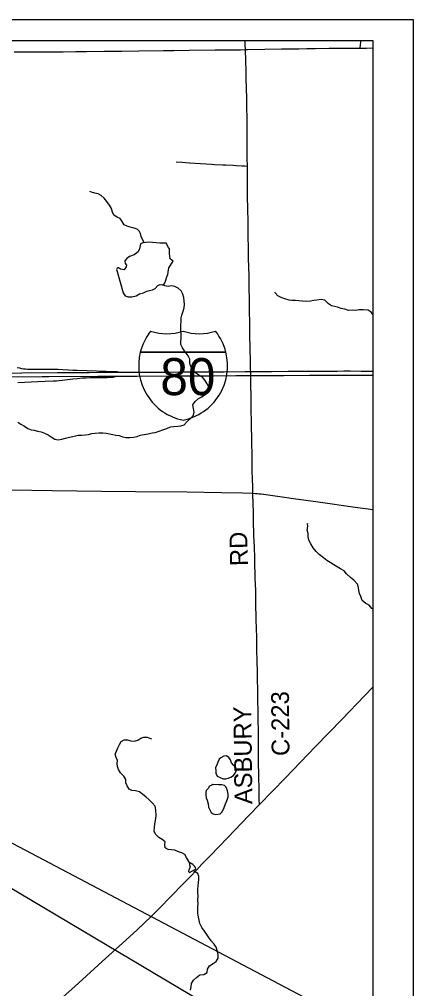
# Model space of a CAD drawing. Extents: x 0 to 34, y 0 to 22.
# Drawn here: x 28.741 to 30.033, y 13.678 to 16.775 of the extents above; entities that cross this region are included whole.
import ezdxf

# ---------------------------------------------------------------- set-up
doc = ezdxf.new("R2010")
doc.units = 0
for name, color, linetype in [('GM_X_Corporation', 7, 'Continuous'), ('GM_X_County_Road', 7, 'Continuous'), ('GM_X_County_Road_Text', 7, 'Continuous'), ('GM_X_Interchange_Ramps', 7, 'Continuous'), ('GM_X_Interstate_Location', 7, 'Continuous'), ('GM_X_Interstate_Route', 7, 'Continuous'), ('GM_X_Interstate_Shield', 7, 'Continuous'), ('GM_X_Minor_Lake', 7, 'Continuous'), ('GM_X_Minor_River', 7, 'Continuous'), ('GM_X_State_Route', 7, 'Continuous'), ('GM_X_Township_Road', 7, 'Continuous'), ('SH_Data', 7, 'Continuous'), ('SH_Text', 7, 'Continuous')]:
    doc.layers.add(name, color=color, linetype=linetype)

msp = doc.modelspace()

# ---------------------------------------------------------------- linework, layer by layer
at = {"layer": 'GM_X_Corporation'}
msp.add_lwpolyline([(29.8715, 12.7899), (29.8715, 16.7067), (27.8821, 16.7067), (27.8849, 16.5038), (27.88, 15.6409), (27.8801, 15.6288), (27.8823, 15.2828), (27.9019, 13.7865), (27.9109, 12.7769)], dxfattribs=at)
at = {"layer": 'GM_X_County_Road'}
for points in [[(28.7244, 16.671), (28.7735, 16.671), (28.8076, 16.6711), (28.8486, 16.6714), (28.8815, 16.6713), (28.9219, 16.672), (28.9561, 16.6725), (29.0126, 16.6733), (29.0692, 16.6736), (29.1232, 16.6741), (29.2022, 16.6749), (29.2345, 16.6754), (29.2838, 16.6762), (29.367, 16.6775), (29.4482, 16.678), (29.4634, 16.6785)], [(29.4634, 16.6785), (29.4699, 16.6787), (29.5251, 16.6795), (29.5792, 16.6803), (29.6053, 16.6807), (29.6345, 16.6812), (29.6593, 16.6814), (29.6873, 16.682), (29.7314, 16.6826), (29.7755, 16.6828), (29.8121, 16.6833), (29.827, 16.6832), (29.8302, 16.6833)], [(29.4698, 16.3059), (29.4696, 16.3314), (29.4694, 16.3737), (29.4691, 16.4147), (29.4687, 16.4632), (29.468, 16.4893), (29.4676, 16.5234), (29.4667, 16.5539), (29.466, 16.5874), (29.4654, 16.6104), (29.4646, 16.6415), (29.4634, 16.6785)], [(29.8302, 16.6833), (29.8506, 16.6834), (29.8715, 16.6844)], [(29.4874, 15.2604), (29.4867, 15.2815), (29.4861, 15.3051), (29.4854, 15.3337), (29.4847, 15.3673), (29.4835, 15.4375), (29.4833, 15.4728), (29.4829, 15.4964), (29.4823, 15.52), (29.4823, 15.5529), (29.4819, 15.5666), (29.4813, 15.6101), (29.481, 15.6231), (29.4807, 15.6368), (29.4807, 15.6393), (29.4804, 15.6497), (29.4803, 15.6561), (29.4797, 15.6759), (29.4793, 15.6921), (29.4789, 15.7144), (29.4783, 15.7355), (29.4778, 15.7536), (29.4774, 15.807), (29.4771, 15.8418), (29.4761, 15.8872), (29.476, 15.9096), (29.4753, 15.9301), (29.4752, 15.9537), (29.4743, 15.9866), (29.4739, 16.0083), (29.4731, 16.0512), (29.4727, 16.0748), (29.4726, 16.0935), (29.4722, 16.1308), (29.4713, 16.1674), (29.4706, 16.2115), (29.4702, 16.2687), (29.4698, 16.3059)], [(29.5086, 14.2655), (29.5079, 14.2809), (29.5075, 14.2902), (29.507, 14.3163), (29.5066, 14.3542), (29.5057, 14.4064), (29.5056, 14.4319), (29.5051, 14.4555), (29.5048, 14.4946), (29.504, 14.5437), (29.5039, 14.5667), (29.5033, 14.5978), (29.5029, 14.6288), (29.5021, 14.6692), (29.5017, 14.6928), (29.501, 14.7214), (29.5002, 14.7618), (29.4995, 14.8003), (29.4982, 14.8562), (29.4972, 14.9127), (29.4964, 14.951), (29.4952, 14.9877), (29.4947, 15.0045), (29.4938, 15.0306), (29.4931, 15.0548), (29.4924, 15.0871), (29.4909, 15.1268), (29.4896, 15.1741), (29.489, 15.2033), (29.4882, 15.2238), (29.4874, 15.2604)]]:
    msp.add_lwpolyline(points, dxfattribs=at)
at = {"layer": 'GM_X_Interchange_Ramps'}
for points in [[(28.7341, 15.6624), (28.7423, 15.6609), (28.7485, 15.6596), (28.7545, 15.6585), (28.7608, 15.6579), (28.7678, 15.6576), (28.7752, 15.6576), (28.8429, 15.6571), (28.8652, 15.6566), (28.8803, 15.656), (28.8981, 15.6552), (28.9118, 15.6544), (28.926, 15.6536), (28.9577, 15.6523), (29.0489, 15.6498), (29.0509, 15.6496), (29.0525, 15.6493), (29.0543, 15.6489), (29.0565, 15.6483), (29.0595, 15.6473)], [(28.737, 15.6146), (28.7583, 15.6154), (28.7789, 15.6162), (28.8001, 15.6173), (28.8239, 15.6184), (28.8507, 15.6197), (28.8605, 15.6202), (28.8687, 15.6208), (28.8785, 15.6216), (28.9125, 15.6257), (28.9267, 15.6273), (28.9427, 15.629), (28.95, 15.6297), (28.9552, 15.6299), (28.9666, 15.63), (28.9763, 15.63), (29.0028, 15.6301), (29.0214, 15.6305), (29.0358, 15.631), (29.0412, 15.6317), (29.0442, 15.6322), (29.0489, 15.6336), (29.0526, 15.6346)]]:
    msp.add_lwpolyline(points, dxfattribs=at)
at = {"layer": 'GM_X_Interstate_Route'}
for points in [[(28.6049, 15.6447), (28.7489, 15.6454), (28.8635, 15.6463), (28.964, 15.6468), (28.9948, 15.647), (29.0595, 15.6473), (29.1062, 15.6473), (29.2094, 15.6479), (29.2656, 15.6482), (29.2958, 15.6484), (29.3406, 15.6487), (29.3957, 15.649), (29.463, 15.6495), (29.4804, 15.6497), (29.495, 15.6498), (29.5466, 15.6501), (29.6004, 15.6503), (29.6301, 15.6504), (29.6796, 15.6507), (29.7571, 15.6512), (29.7779, 15.6514), (29.7981, 15.6513), (29.833, 15.6512), (29.8623, 15.6506), (29.8715, 15.6505)], [(28.4183, 15.6309), (28.5497, 15.6317), (28.6303, 15.6322), (28.7018, 15.6327), (28.8137, 15.6335), (28.835, 15.6337), (28.9922, 15.6344), (29.0526, 15.6346), (29.0786, 15.6347), (29.1177, 15.635), (29.2238, 15.6356), (29.2846, 15.6359), (29.359, 15.6363), (29.4331, 15.6366), (29.4807, 15.6368), (29.4864, 15.6368), (29.5351, 15.6371), (29.5866, 15.6373), (29.6684, 15.6378), (29.7399, 15.6382), (29.7723, 15.6384), (29.8513, 15.6383), (29.8631, 15.638), (29.8715, 15.6378)]]:
    msp.add_lwpolyline(points, dxfattribs=at)
at = {"layer": 'GM_X_Interstate_Shield'}
for p, q in [((29.1278, 15.7117), (29.4011, 15.7117)), ((29.4011, 15.7117), (29.1278, 15.7117)), ((29.4011, 15.7117), (29.1278, 15.7117))]:
    msp.add_line(p, q, dxfattribs=at)
for centre, start, end in [((29.3, 15.6681), 141.669, 165.8066), ((29.2126, 15.9481), 253.0091, 286.9909), ((29.3163, 15.9481), 253.0091, 286.9909), ((29.2289, 15.6681), 14.1934, 38.331), ((29.3, 15.6681), 165.8066, 258.463), ((29.2289, 15.6681), 281.537, 14.1934)]:
    msp.add_arc(centre, 0.1776, start, end, dxfattribs=at)
at = {"layer": 'GM_X_Minor_Lake'}
for p, q in [((29.0541, 15.969), (29.0726, 15.9012)), ((29.3738, 14.3564), (29.3925, 14.3483)), ((29.3771, 14.3291), (29.3593, 14.33)), ((29.2852, 14.0481), (29.3044, 14.059))]:
    msp.add_line(p, q, dxfattribs=at)
for points in [[(29.0726, 15.9012), (29.0796, 15.891), (29.0894, 15.8885), (29.1004, 15.8882), (29.114, 15.8918), (29.1249, 15.8973), (29.1378, 15.9012), (29.1491, 15.9067), (29.1574, 15.9087), (29.1672, 15.911), (29.1751, 15.9149), (29.1833, 15.9245), (29.1916, 15.9273), (29.1988, 15.9266), (29.2052, 15.9312), (29.2078, 15.9381), (29.2126, 15.9522), (29.2155, 15.9591), (29.217, 15.9667), (29.2191, 15.9808), (29.2329, 16.0018), (29.2233, 16.0101), (29.2208, 16.0271), (29.2214, 16.0419), (29.218, 16.0461), (29.2106, 16.0593), (29.1906, 16.0594), (29.1784, 16.0604), (29.1553, 16.0624), (29.136, 16.0611), (29.1281, 16.0572), (29.1256, 16.0412), (29.1204, 16.032), (29.1084, 16.022), (29.0937, 16.0173), (29.0843, 16.0103), (29.0783, 16.0031), (29.0795, 15.9943), (29.0838, 15.9891), (29.0823, 15.9841), (29.0764, 15.9749), (29.0646, 15.9771), (29.0585, 15.9804), (29.0547, 15.9807), (29.0536, 15.9796), (29.0517, 15.9758), (29.0541, 15.969)], [(29.3925, 14.3483), (29.4008, 14.348), (29.4083, 14.3496), (29.417, 14.3535), (29.4253, 14.3581), (29.4309, 14.3658), (29.4353, 14.3757), (29.433, 14.3841), (29.4268, 14.3901), (29.4188, 14.3991), (29.4156, 14.4085), (29.411, 14.4165), (29.403, 14.4217), (29.3943, 14.4204), (29.3845, 14.4154), (29.3796, 14.4104), (29.3752, 14.4012), (29.3723, 14.3928), (29.3678, 14.3833), (29.3691, 14.3731), (29.3692, 14.3658), (29.3738, 14.3564)], [(29.3593, 14.33), (29.3559, 14.3281), (29.3484, 14.3242), (29.344, 14.3166), (29.3383, 14.3104), (29.3369, 14.3051), (29.337, 14.2963), (29.3382, 14.2872), (29.3417, 14.2793), (29.3449, 14.268), (29.3457, 14.2573), (29.3504, 14.2464), (29.3539, 14.24), (29.3607, 14.2362), (29.3687, 14.2337), (29.3827, 14.2361), (29.3891, 14.243), (29.3961, 14.2564), (29.3998, 14.2682), (29.4046, 14.2778), (29.4086, 14.29), (29.4085, 14.2987), (29.4065, 14.3101), (29.4034, 14.3188), (29.4015, 14.3225), (29.3965, 14.3263), (29.3885, 14.3289), (29.3771, 14.3291)], [(29.3044, 14.059), (29.3051, 14.0605), (29.3036, 14.0651), (29.3009, 14.0684), (29.2951, 14.0741), (29.2902, 14.0774), (29.2875, 14.0804), (29.2849, 14.0766), (29.2853, 14.0728), (29.2869, 14.0668), (29.2862, 14.063), (29.2832, 14.0576), (29.2821, 14.0523), (29.2844, 14.0485), (29.2852, 14.0481)]]:
    msp.add_lwpolyline(points, dxfattribs=at)
at = {"layer": 'GM_X_Minor_River'}
for points in [[(29.125, 16.097), (29.1175, 16.1048), (29.1076, 16.1078), (29.0958, 16.1108), (29.0855, 16.1145), (29.076, 16.1187), (29.0703, 16.1289), (29.0634, 16.1387), (29.0535, 16.1425), (29.0436, 16.1497), (29.0394, 16.1591), (29.0356, 16.1701), (29.0294, 16.1815), (29.0207, 16.1925), (29.0126, 16.2039), (29.0024, 16.2122), (28.9928, 16.2171), (28.9822, 16.22), (28.9719, 16.223), (28.967, 16.2245)], [(29.14, 16.0614), (29.1347, 16.0713), (29.1309, 16.0811), (29.1281, 16.091), (29.125, 16.097)], [(28.7885, 15.4623), (28.7988, 15.4594), (28.8113, 15.4565), (28.8212, 15.4528), (28.833, 15.4472), (28.8425, 15.4413), (28.8551, 15.4334), (28.8657, 15.4309), (28.8771, 15.4337), (28.8892, 15.4369), (28.9012, 15.4397), (28.9122, 15.4421), (28.9296, 15.4457), (28.9398, 15.4458), (28.9523, 15.4475), (28.9625, 15.4487), (28.9727, 15.4511), (28.9837, 15.4528), (28.995, 15.4533), (29.0075, 15.4538), (29.0185, 15.4521), (29.0291, 15.4503), (29.0401, 15.4485), (29.0496, 15.4464), (29.0606, 15.4446), (29.0724, 15.4405), (29.0819, 15.4391), (29.0948, 15.4385), (29.1058, 15.4398), (29.1175, 15.4422), (29.1277, 15.4457), (29.1401, 15.4482), (29.1526, 15.4502), (29.1655, 15.4538), (29.1753, 15.4543), (29.1885, 15.459), (29.2002, 15.4629), (29.2123, 15.4672), (29.2247, 15.4723), (29.2349, 15.4736), (29.2474, 15.4749), (29.2576, 15.4761), (29.2682, 15.4793), (29.2775, 15.4896), (29.2892, 15.5004), (29.2974, 15.5104), (29.3003, 15.5199), (29.2972, 15.5317), (29.2959, 15.543), (29.303, 15.5537), (29.3138, 15.5634), (29.3244, 15.5692), (29.3357, 15.5769), (29.3446, 15.5869), (29.3472, 15.5972), (29.3417, 15.61), (29.3348, 15.6213), (29.326, 15.6311), (29.3145, 15.6382), (29.3027, 15.646), (29.2931, 15.6569), (29.2885, 15.6675), (29.2857, 15.6777), (29.2859, 15.6895), (29.2809, 15.6997), (29.2713, 15.7121), (29.2621, 15.7257), (29.2574, 15.7359), (29.2569, 15.7454), (29.2579, 15.7575), (29.2578, 15.7682), (29.2573, 15.778), (29.2576, 15.7879), (29.2571, 15.7985), (29.2581, 15.8092), (29.2584, 15.8206), (29.2605, 15.8301), (29.2649, 15.8427), (29.2678, 15.8526), (29.2685, 15.8644), (29.2676, 15.8746), (29.2663, 15.886), (29.2636, 15.8966), (29.2578, 15.9075), (29.2482, 15.9158), (29.2383, 15.9217), (29.2273, 15.9231), (29.2171, 15.9215), (29.2061, 15.9233), (29.1988, 15.9266)], [(29.8715, 15.8307), (29.8649, 15.839), (29.8554, 15.8461), (29.8394, 15.8467), (29.8273, 15.8462), (29.8164, 15.8445), (29.8057, 15.8452), (29.7925, 15.8446), (29.7811, 15.8483), (29.7689, 15.8505), (29.7579, 15.8553), (29.748, 15.8574), (29.7385, 15.86), (29.729, 15.8663), (29.7171, 15.8772), (29.7058, 15.8793), (29.6918, 15.878), (29.6815, 15.8768), (29.6713, 15.874), (29.6589, 15.8735), (29.6452, 15.8745), (29.6338, 15.8755), (29.6232, 15.8761), (29.6122, 15.8767), (29.6028, 15.8778), (29.5895, 15.8814), (29.578, 15.8862), (29.567, 15.891), (29.5586, 15.9008), (29.5574, 15.9027)], [(28.7363, 15.4875), (28.7459, 15.4815), (28.7573, 15.4752), (28.768, 15.4674), (28.7787, 15.4629), (28.7885, 15.4623)], [(29.8715, 14.8896), (29.8674, 14.8927), (29.8586, 14.9025), (29.8487, 14.9084), (29.8368, 14.9181), (29.8318, 14.9306), (29.8275, 14.9404), (29.8263, 14.9499), (29.8243, 14.9598), (29.8215, 14.9696), (29.81, 14.9832), (29.7993, 14.9914), (29.7867, 15.003), (29.779, 15.0128), (29.7675, 15.0195), (29.7565, 15.0251), (29.7458, 15.0322), (29.7348, 15.0389), (29.7241, 15.046), (29.7126, 15.0546), (29.6992, 15.065), (29.6897, 15.0744), (29.6805, 15.0861), (29.6724, 15.0993), (29.6662, 15.111), (29.6638, 15.1212), (29.6637, 15.1322), (29.6605, 15.1421), (29.6627, 15.1539)], [(29.6627, 15.1539), (29.6618, 15.1637), (29.6618, 15.163)], [(29.2862, 14.0786), (29.2752, 14.0962), (29.2705, 14.1065), (29.2599, 14.1116), (29.2496, 14.1142), (29.2382, 14.1197), (29.2272, 14.1215), (29.217, 14.1222), (29.2074, 14.127), (29.2066, 14.1365), (29.2076, 14.1471), (29.198, 14.1542), (29.187, 14.1605), (29.1774, 14.1699), (29.172, 14.1797), (29.173, 14.1919), (29.174, 14.2044), (29.1765, 14.2143), (29.1779, 14.2292), (29.1777, 14.2493), (29.1756, 14.261), (29.1661, 14.2716), (29.1565, 14.2813), (29.1454, 14.2903), (29.1359, 14.2978), (29.1252, 14.306), (29.1119, 14.31), (29.1012, 14.3111), (29.0917, 14.3147), (29.0859, 14.3253), (29.082, 14.3351), (29.0815, 14.3462), (29.0746, 14.3563), (29.0643, 14.3672), (29.0581, 14.3774), (29.0549, 14.3872), (29.0541, 14.3967), (29.0544, 14.4062), (29.0508, 14.416), (29.0473, 14.4266), (29.0521, 14.4366), (29.0562, 14.4465), (29.0614, 14.4576), (29.0666, 14.4675), (29.0763, 14.4729), (29.0866, 14.4723), (29.098, 14.4698), (29.1086, 14.468), (29.1199, 14.4712), (29.1297, 14.4777), (29.1395, 14.4816), (29.1497, 14.481), (29.1604, 14.4773), (29.1638, 14.4759)], [(29.2879, 13.6722), (29.2904, 13.6832), (29.291, 13.6935), (29.2973, 13.7046), (29.3071, 13.7134), (29.318, 13.7212), (29.3308, 13.7225), (29.341, 13.7294), (29.3428, 13.7401), (29.3491, 13.75), (29.36, 13.7574), (29.3701, 13.7643), (29.3768, 13.775), (29.3767, 13.786), (29.374, 13.7966), (29.3696, 13.8095), (29.3642, 13.8193), (29.3539, 13.8306), (29.347, 13.8411), (29.3408, 13.8509), (29.3323, 13.8611), (29.3246, 13.8731), (29.3184, 13.8852), (29.316, 13.8958), (29.314, 13.9061), (29.3116, 13.9186), (29.3114, 13.9387), (29.3128, 13.9482), (29.3115, 13.96), (29.3129, 13.9729), (29.3113, 13.985), (29.3119, 13.9949), (29.3125, 14.0063), (29.3132, 14.0166), (29.3142, 14.0261), (29.3145, 14.0356), (29.311, 14.0454), (29.3014, 14.0521), (29.2977, 14.0552)]]:
    msp.add_lwpolyline(points, dxfattribs=at)
at = {"layer": 'GM_X_State_Route'}
for points in [[(28.715, 15.271), (28.8462, 15.2696), (29.0041, 15.2677), (29.1128, 15.2661), (29.2776, 15.2647), (29.3876, 15.2632), (29.4547, 15.2616), (29.4874, 15.2604), (29.4957, 15.2601), (29.5019, 15.2596), (29.5075, 15.2591), (29.5137, 15.2584), (29.5211, 15.2574), (29.5734, 15.2503), (29.617, 15.2441), (29.6957, 15.233), (29.8143, 15.2163), (29.8715, 15.2085)], [(28.8818, 13.6509), (28.9186, 13.6843), (29.0058, 13.764), (29.0707, 13.8229), (29.1162, 13.8643), (29.1426, 13.8889), (29.1618, 13.9074), (29.1825, 13.9281), (29.2309, 13.9775), (29.2594, 14.0071), (29.2866, 14.035), (29.3071, 14.0562), (29.3248, 14.0748), (29.3505, 14.1016), (29.4061, 14.1595), (29.4748, 14.2305), (29.5086, 14.2655), (29.5914, 14.3512), (29.6878, 14.4517), (29.7721, 14.5387), (29.8435, 14.6132), (29.8715, 14.6422)]]:
    msp.add_lwpolyline(points, dxfattribs=at)
at = {"layer": 'GM_X_Township_Road'}
for points in [[(29.4634, 16.6785), (29.463, 16.6925), (29.4627, 16.7067)], [(29.8302, 16.6833), (29.8314, 16.6943), (29.832, 16.701), (29.8322, 16.7067)], [(29.2426, 16.3197), (29.2618, 16.3187), (29.2854, 16.3169), (29.3033, 16.3156), (29.3547, 16.3119), (29.3646, 16.3114), (29.3916, 16.3105), (29.4007, 16.3102), (29.424, 16.3091), (29.4339, 16.3083), (29.4531, 16.3072), (29.4605, 16.3066), (29.4698, 16.3059)]]:
    msp.add_lwpolyline(points, dxfattribs=at)
at = {"layer": 'SH_Data'}
for p, q in [((22.9992, 16.7749), (29.9992, 16.7749)), ((29.9992, 16.7749), (29.9992, 9.7749))]:
    msp.add_line(p, q, dxfattribs=at)
at = {"layer": 'SH_Text'}
msp.add_lwpolyline([(30.3847, 13.262), (26.5546, 15.2831), (30.3847, 13.0053)], close=True, dxfattribs=at)

# ---------------------------------------------------------------- texts
at = {"layer": 'GM_X_County_Road_Text'}
for s, rotation, p in [('RD', 91.4825, (29.4717, 15.0286)), ('C-223', 90.5521, (29.6044, 14.4212)), ('ASBURY', 90.6776, (29.4858, 14.2671))]:
    msp.add_text(s, height=0.05682, rotation=rotation, dxfattribs=at).set_placement(p)
at = {"layer": 'GM_X_Interstate_Location'}
for s in ['.', '-', ',']:
    msp.add_text(s, height=0.000189, dxfattribs=at).set_placement((29.2644, 15.6361))
msp.add_text('80', height=0.000189, rotation=0, dxfattribs=at).set_placement((29.2257, 15.5969))
at = {"layer": 'GM_X_Interstate_Shield'}
msp.add_text('80', height=0.11837, dxfattribs=at).set_placement((29.1917, 15.5741))

doc.saveas('drawing.dxf')
